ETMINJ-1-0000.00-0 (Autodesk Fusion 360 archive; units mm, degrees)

design "ETMINJ-1-0000.00-0" references "Motor HP 1740", "ETMINJ-1-1000.00-0", "ETMINJ-1-2000.00-0", "Pulley ID25,4", "ETMINJ-1-4000.00-0", "ETMINJ-1-3000.00-0"
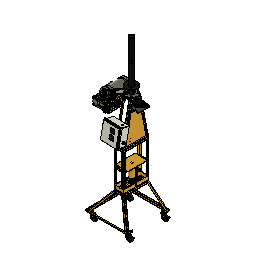
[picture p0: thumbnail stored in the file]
description: El Tornillo Motored Injection Machine
component_insert "Component Insert1"
ground "Ground1"
component_insert "Component Insert2"
component_insert "Component Insert3"
joint "Assemble7" alignAngle 90 alignOffsetX 0 alignOffsetY 0 alignOffsetZ 0
joint "Assemble3" alignAngle 0 alignOffsetX 0 alignOffsetY 0 alignOffsetZ 0
component_insert "Component Insert4"
joint "Assemble4" alignAngle -90 alignOffsetX 0 alignOffsetY -25 alignOffsetZ 100
component_insert "Component Insert5"
joint "Assemble5" alignAngle -90 alignOffsetX 0 alignOffsetY 0 alignOffsetZ 0
component_insert "Component Insert6"
joint "Assemble6" alignAngle 180 alignOffsetX 0 alignOffsetY 0 alignOffsetZ -2

design "Bearing DI28-DO52"
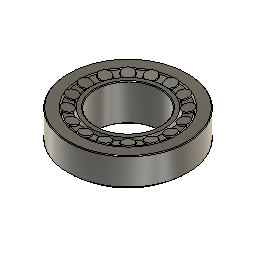
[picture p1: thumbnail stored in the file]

design "V-Belt_TypeA_L610"
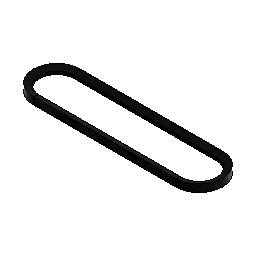
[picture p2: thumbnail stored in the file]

design "ETMINJ-1-1100.08-0"
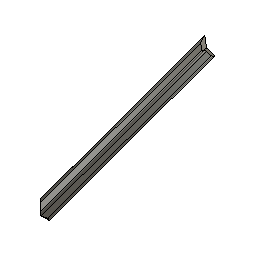
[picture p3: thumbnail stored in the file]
description: Frame base angle 8

design "ETMINJ-1-2110.00-0" references "ETMINJ-1-2110.02-0", "ETMINJ-1-2110.01-0"
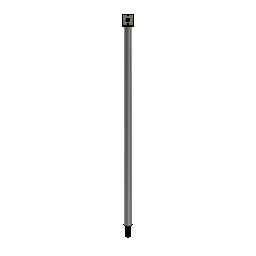
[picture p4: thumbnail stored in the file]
description: Piston (welding) sub-sub assy
component_insert "Component Insert1"
joint "Assemble1" alignAngle 0 alignOffsetX 0 alignOffsetY 0 alignOffsetZ 0
component_insert "Component Insert2"
joint "Assemble2" alignAngle 45 alignOffsetX 0 alignOffsetY 0 alignOffsetZ 0
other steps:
joint_origin "JointOrigin1"

design "ETMINJ-1-3100.01-0"
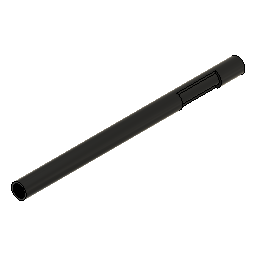
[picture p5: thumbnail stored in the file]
description: Barrel tube

design "Heating band_D35-H50mm_110V"
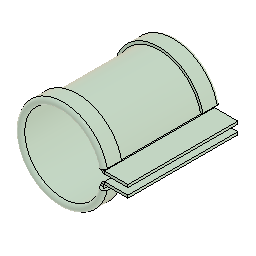
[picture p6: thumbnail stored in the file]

design "ETMINJ-1-1300.00-0" references "ETMINJ-1-1320.00-0", "ETMINJ-1-1300.01-0", "ISO 7040-M8", "ISO 7089-M8-8.8", "ISO 4014-M8x65-8.8", "ETMINJ-1-1310.00-0"
description: Piston holder sub assy
component_insert "Component Insert1"
ground "Ground1"
component_insert "Component Insert2"
component_insert "Component Insert3"
component_insert "Component Insert4"
joint "Assemble1" alignAngle 180 alignOffsetX 0 alignOffsetY 0 alignOffsetZ 0
joint "Assemble2" alignAngle 90 alignOffsetX 0 alignOffsetY 0 alignOffsetZ -3.2
joint "Assemble3" alignAngle 90 alignOffsetX 0 alignOffsetY 0 alignOffsetZ -3.2
component_insert "Component Insert5"
joint "Assemble4" alignAngle -90 alignOffsetX 0 alignOffsetY 0 alignOffsetZ 0
component_insert "Component Insert6"
joint "Assemble5" alignAngle -90 alignOffsetX 0 alignOffsetY 0 alignOffsetZ 0
component_insert "Component Insert7"
joint "Assemble6" alignAngle 0 alignOffsetX 0 alignOffsetY 0 alignOffsetZ 0
component_insert "Component Insert8"
joint "Assemble7" alignAngle 0 alignOffsetX 0 alignOffsetY 0 alignOffsetZ 0
component_insert "Component Insert9"
component_insert "Component Insert10"
joint "Assemble10" alignAngle 0 alignOffsetX 0 alignOffsetY 0 alignOffsetZ 0
joint "Assemble11" alignAngle 90 alignOffsetX 0 alignOffsetY 0 alignOffsetZ 0
component_insert "Component Insert11"
joint "Assemble12" alignAngle 0 alignOffsetX 0 alignOffsetY 0 alignOffsetZ 0
component_insert "Component Insert12"
joint "Assemble13" alignAngle 90 alignOffsetX 0 alignOffsetY 0 alignOffsetZ 0

design "ETMINJ-1-1320.02-0"
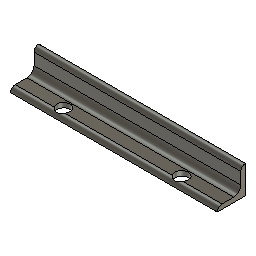
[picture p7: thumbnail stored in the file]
description: Reducer support - Angle

design "ETMINJ-1-1310.07-0"
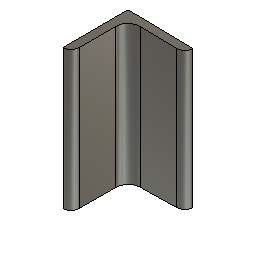
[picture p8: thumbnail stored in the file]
description: Piston holder frame angle 7
base_feature "Base Feature"
split "Split1"
remove_body "RemoveBody1"
remove_body "RemoveBody2"

design "ETMINJ-1-1100.00-0" references "ETMINJ-1-1100.07-0", "ETMINJ-1-1100.08-0", "ETMINJ-1-1100.04-0", "ETMINJ-1-1100.09-0", "ETMINJ-1-1100.05-0", "ETMINJ-1-1100.06-0", "ETMINJ-1-1100.03-0", "ETMINJ-1-1100.01-0", "ETMINJ-1-1100.02-0"
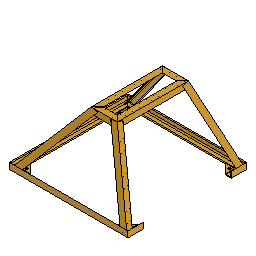
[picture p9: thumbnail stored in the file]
description: Frame base (welding) sub assy
description: Frame base angle 5
description: Frame base angle 8
component_insert "Component Insert1"
joint "Assemble1" alignAngle 90 alignOffsetX 0 alignOffsetY 0 alignOffsetZ 0
component_insert "Component Insert2"
component_insert "Component Insert3"
joint "Assemble2" alignAngle 0 alignOffsetX 0 alignOffsetY 0 alignOffsetZ 0
joint "Assemble3" alignAngle 180 alignOffsetX 0 alignOffsetY 0 alignOffsetZ 0
component_insert "Component Insert4"
joint "Assemble4" alignAngle 180 alignOffsetX 0 alignOffsetY 0 alignOffsetZ 0
component_insert "Component Insert5"
component_insert "Component Insert6"
component_insert "Component Insert7"
joint "Assemble5" alignAngle 180 alignOffsetX 0 alignOffsetY 0 alignOffsetZ 0
joint "Assemble6" alignAngle 0 alignOffsetX 0 alignOffsetY 0 alignOffsetZ 0
joint "Assemble7" alignAngle 180 alignOffsetX 245 alignOffsetY 300 alignOffsetZ 0
component_insert "Component Insert8"
joint "Assemble16" alignAngle -90 alignOffsetX 0 alignOffsetY 0 alignOffsetZ 0
position "Position1"
as_built_joint "As-built2"
mirror_component "MirrorComponent1"
derived_instance "DerivedInstance1"
derived_instance "DerivedInstance1"
component_insert "Component Insert10"
joint "Assemble9" alignAngle 0 alignOffsetX 0 alignOffsetY 0 alignOffsetZ 0
component_insert "Component Insert11"
joint "Assemble10" alignAngle 180 alignOffsetX 0 alignOffsetY 0 alignOffsetZ 0
component_insert "Component Insert12"
joint "Assemble11" alignAngle 180 alignOffsetX 0 alignOffsetY 0 alignOffsetZ 0
mirror_component "MirrorComponent2"
derived_instance "DerivedInstance2"
component_insert "Component Insert13"
joint "Assemble12" alignAngle 180 alignOffsetX -2.6 alignOffsetY 0 alignOffsetZ 0
component_insert "Component Insert14"
joint "Assemble13" alignAngle 180 alignOffsetX -2.6 alignOffsetY 0 alignOffsetZ 0
component_insert "Component Insert15"
joint "Assemble14" alignAngle -90 alignOffsetX 0 alignOffsetY -2.6 alignOffsetZ 0
component_insert "Component Insert16"
joint "Assemble15" alignAngle 0 alignOffsetX 2.6 alignOffsetY 0 alignOffsetZ 0
as_built_joint "As-built1"
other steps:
derived_base_feature "Derived Base Feature1"
derived_base_feature "Derived Base Feature1"
derived_base_feature "Derived Base Feature"
joint_origin "JointOrigin1"
create_component "CreateComponent1"
create_component "CreateComponent2"
create_component "CreateComponent3"

design "UpDown Switch"
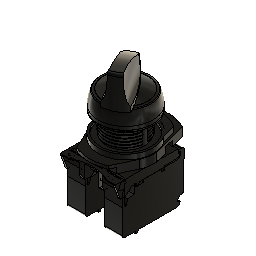
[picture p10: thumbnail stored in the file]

design "ISO 7040-M10"
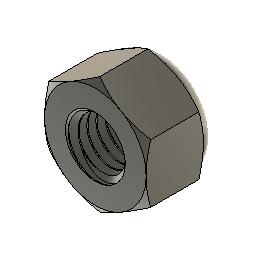
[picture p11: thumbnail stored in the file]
base_feature "Base Feature"

design "Hydraulic jack 2 Tons_Min.180-Max.350"
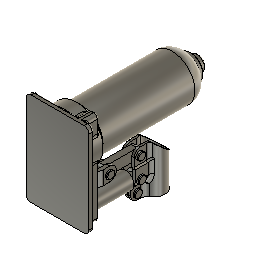
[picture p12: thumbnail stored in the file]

design "ISO 7040-M6"
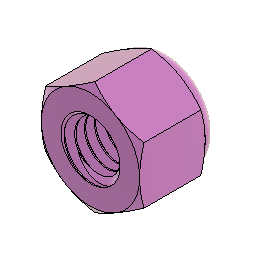
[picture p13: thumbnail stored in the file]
base_feature "Base Feature"

design "ETMINJ-1-1210.05-0"
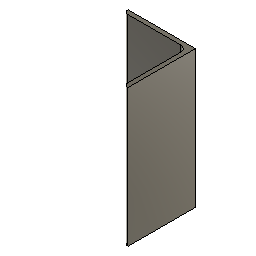
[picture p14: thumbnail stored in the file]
description: Jack holder frame angle 5

design "ETMINJ-1-2300.01-0"
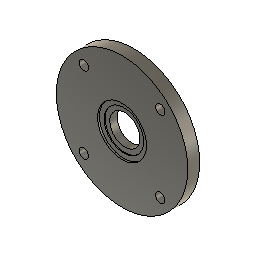
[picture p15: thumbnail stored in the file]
base_feature "Base Feature"

design "ETMINJ-1-1310.08-0"
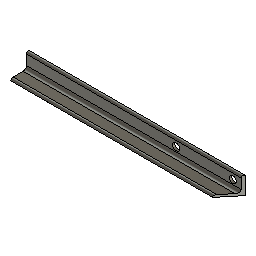
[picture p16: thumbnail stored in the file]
description: Piston holder frame angle 8

design "Pulley ID36"
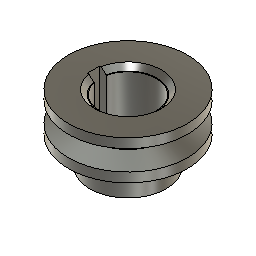
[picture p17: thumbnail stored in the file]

design "ISO 4762-M4x40"
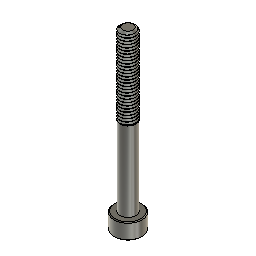
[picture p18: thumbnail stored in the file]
base_feature "Base Feature"

design "ISO 7089-M8-8.8"
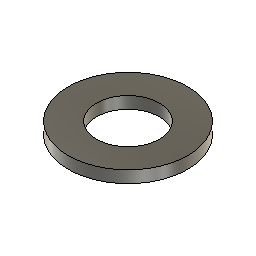
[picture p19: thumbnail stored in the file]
base_feature "Basiselement"

design "ETMINJ-1-1220.01-0"
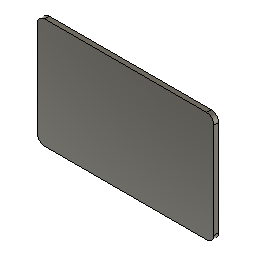
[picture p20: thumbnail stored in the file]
description: Mould base plate

design "ETMINJ-1-1100.05-0"
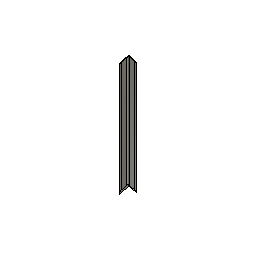
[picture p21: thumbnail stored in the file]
description: Frame base angle 5

design "ETMINJ-1-2100.01-0"
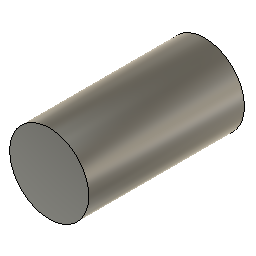
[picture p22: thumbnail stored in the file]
description: Piston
